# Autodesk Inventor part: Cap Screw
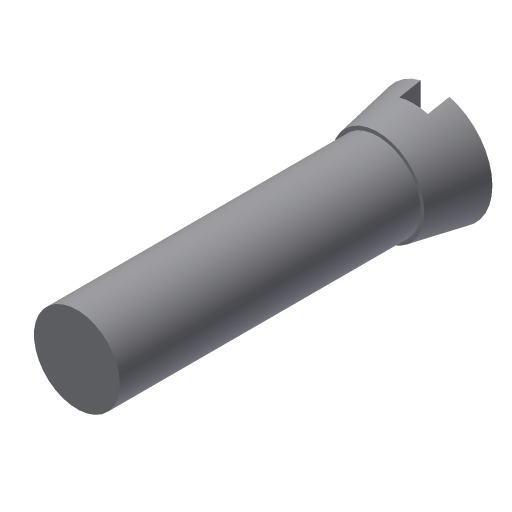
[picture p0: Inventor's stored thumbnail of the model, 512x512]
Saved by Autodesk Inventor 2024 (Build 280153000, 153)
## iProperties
Shininess: 77.0
Length Units: 11269
Angle Units: 11279
Time Units: 11290
Mass Units: 11283
Length Display Precision: 3
Angle Display Precision: 2
Created: 2002-02
Part Number: Cap Screw
Document SubType Name: Modeling
Designer: ***
Density: 1 g/cm^3
Material: Generic
Mass: 0.736586 g
Surface Area: 5.87035 cm^2
Volume: 0.736586 cm^3
Appearance: Default
Density: 0.0
Volumn: 0.0
Area: 0.0
PropertySet Name: Model Information
Control State: 0
Master: False
Checked Out: False
Author: ***
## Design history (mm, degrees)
sketch "Sketch1"
  geometry: L1 (0, 27.83)-(4, 27.83); L2 (4, 27.83)-(3.25, 23.83); L3 (3.25, 23.83)-(0, 23.83); L4 (0, 23.83)-(0, 27.83)
  constraints: 8 end point, 1 horizontal, 1 parallel, 1 perpendicular, 1 point on line
  dimensions: "d2" = 4 distance from line of L1 L2.end; "d5" = 8 diameter of L1.end L4; "d6" = 6.5 diameter of L3.start L4; "d14" = 4 distance of L3.end L1.start
revolve "Revolution1" sketch "Sketch1" stored, may be unused: angle "d7" = 90 deg
sketch "Sketch2"
  geometry: C1 r 3 at (0, 0)
  constraints: 1 centre point
  dimensions: "d8" = 6 diameter of C1
extrude "Extrusion1" join sketch "Sketch2" distance "d9" = 21; taper "d10" = 0 deg
sketch "Sketch3"
  geometry: L1 (-1, 28.967)-(1, 28.967); L2 (1, 28.967)-(1, 26.33); L3 (1, 26.33)-(-1, 26.33); L4 (-1, 26.33)-(-1, 28.967); L5 (-4, 27.83)-(4, 27.83) reference
  constraints: 8 end point, 2 parallel, 1 horizontal, 1 perpendicular
  dimensions: "d11" = 2 distance of L1.start L1.end; "d15" = 1.5 distance between parallel lines of L5 L3
extrude "Extrusion2" cut sketch "Sketch3" extent not by distance; stored distance "d12" = 24; taper "d13" = 0 deg
body "Solid1"
